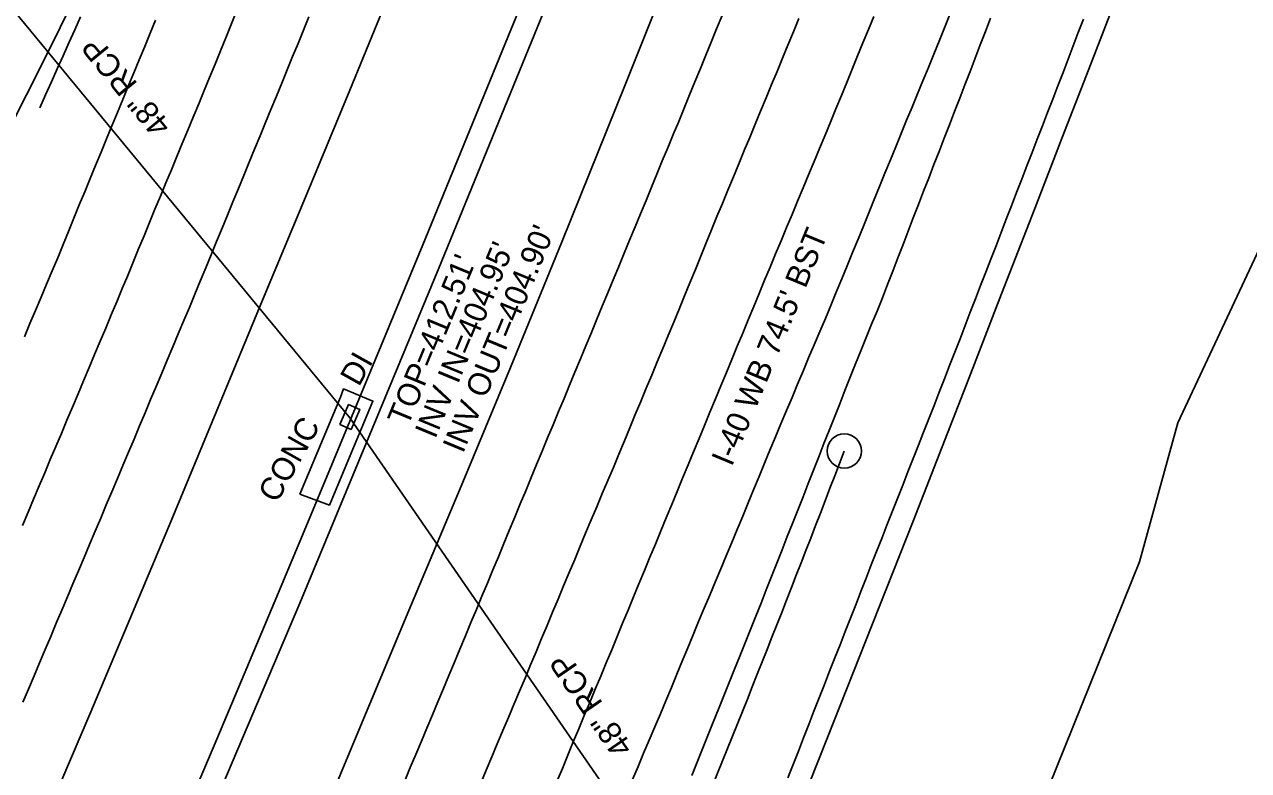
# Model space of a CAD drawing. Extents: x 2074109 to 2077820, y 741079 to 746031.
# Drawn here: x 2076109.6 to 2076324, y 744579.2 to 744709.8 of the extents above; entities that cross this region are included whole.
import ezdxf

# ---------------------------------------------------------------- set-up
doc = ezdxf.new("R2010")
doc.units = 0
for name, color, linetype in [('Exist Guardrail Cable Guide Rail', 7, 'Continuous'), ('Exist Horizontal Alignment', 7, 'Continuous'), ('Exist Horizontal Alignment Point', 7, 'Continuous'), ('Exist Roads EOP', 7, 'Continuous'), ('Exist Roads EOP Text', 7, 'Continuous'), ('Exist Roads EOT', 7, 'Continuous'), ('Exist Structure Minor Drop Inlet', 7, 'Continuous'), ('Exist Structure Minor Drop Inlet Text', 7, 'Continuous'), ('Exist Structure Minor Drop Inlet Top Elevation', 7, 'Continuous'), ('Exist Structure Minor Paved Ditch or Gutter', 7, 'Continuous'), ('Exist Structure Minor Paved Ditch or Gutter Text', 7, 'Continuous'), ('Exist Structure Minor Pipes RCP 48 Inch', 7, 'Continuous'), ('Exist Structure Minor Pipes RCP 48 Inch Invert', 7, 'Continuous'), ('Exist Structure Minor Pipes RCP 48 Inch Text', 7, 'Continuous'), ('Exist Vegetation Woods Line', 7, 'Continuous')]:
    doc.layers.add(name, color=color, linetype=linetype)

msp = doc.modelspace()

# ---------------------------------------------------------------- linework, layer by layer
at = {"layer": 'Exist Guardrail Cable Guide Rail'}
for points in [[(2076157.81, 744608.48), (2076182.17, 744667.13), (2076200.46, 744711.79), (2076224.74, 744772.31), (2076248.56, 744832.55), (2076283.35, 744922.09), (2076306.06, 744981.77), (2076321.31, 745022.08)], [(2075948.31, 744139.02), (2075989.39, 744226.34), (2076023.39, 744300.35), (2076049.61, 744359.61), (2076088.84, 744447.64), (2076120.46, 744520.55), (2076157.81, 744608.48)]]:
    msp.add_lwpolyline(points, dxfattribs=at)
at = {"layer": 'Exist Horizontal Alignment'}
for centre, radius, start, end in [((2065746.77, 748969.72), 11283.45, 330.581241, 339.398504), ((2074798.58, 745361.18), 1469.76, 306.18995, 339.08912), ((2073514.74, 745680.24), 2931.09, 337.65302, 339.11117)]:
    msp.add_arc(centre, radius, start, end, dxfattribs=at)
at = {"layer": 'Exist Horizontal Alignment Point'}
msp.add_circle((2076253.18, 744635.14), 3, dxfattribs=at)
at = {"layer": 'Exist Roads EOP'}
for points in [[(2076301.38, 744917.71), (2076290.05, 744888.4), (2076279.13, 744860.68), (2076268.89, 744834.6), (2076259.62, 744810.96), (2076250.46, 744787.8), (2076239.27, 744760.09), (2076226.77, 744729.15), (2076214.82, 744699.23), (2076203.77, 744671.9), (2076194.71, 744649.77), (2076186.11, 744628.98), (2076176.93, 744607.21), (2076166.52, 744582.37), (2076156.08, 744557.21), (2076146.17, 744533.97), (2076137.36, 744513.8), (2076127.55, 744490.96), (2076117.74, 744468.19), (2076107.5, 744444.68), (2076097.57, 744422.1), (2076087.78, 744400.15), (2076077.87, 744377.58), (2076066.3, 744351.92)], [(2076017.34, 744351.57), (2076024.53, 744367.7), (2076032.16, 744384.78), (2076040.54, 744403.58), (2076049.71, 744424.28), (2076058.18, 744443.41), (2076065.39, 744459.74), (2076072.98, 744477.03), (2076081.56, 744496.75), (2076090.68, 744517.93), (2076100.09, 744540.01), (2076106.65, 744555.4), (2076114.28, 744573.21), (2076121.23, 744589.47), (2076128.09, 744605.72), (2076135.28, 744622.91), (2076143.19, 744641.95), (2076151.31, 744661.52), (2076159.11, 744680.25), (2076166.6, 744698.31), (2076173.8, 744715.85)], [(2076299.7, 744711.5), (2076295.58, 744700.96), (2076291.35, 744690.03), (2076286.56, 744677.62), (2076280.74, 744662.65), (2076274.97, 744647.82), (2076270.34, 744635.86), (2076265.26, 744622.84), (2076258.12, 744604.87), (2076250.1, 744584.72), (2076242.34, 744565.18)]]:
    msp.add_lwpolyline(points, dxfattribs=at)
at = {"layer": 'Exist Roads EOT'}
for points in [[(2076109.27, 744622.11), (2076110.24, 744624.42), (2076111.22, 744626.72), (2076112.19, 744629.02), (2076113.16, 744631.32), (2076114.14, 744633.63), (2076115.12, 744635.93), (2076116.09, 744638.23), (2076117.06, 744640.54), (2076118.03, 744642.84), (2076119, 744645.14), (2076119.97, 744647.45), (2076120.93, 744649.75), (2076121.9, 744652.06), (2076122.87, 744654.36), (2076123.84, 744656.67), (2076124.81, 744658.97), (2076125.78, 744661.28), (2076126.75, 744663.58), (2076127.71, 744665.89), (2076128.66, 744668.2), (2076129.61, 744670.51), (2076130.56, 744672.83), (2076131.51, 744675.14), (2076132.47, 744677.45), (2076133.43, 744679.76), (2076134.38, 744682.07), (2076135.34, 744684.38), (2076136.3, 744686.68), (2076137.25, 744688.99), (2076138.21, 744691.3), (2076139.17, 744693.61), (2076140.12, 744695.92), (2076141.08, 744698.23), (2076142.04, 744700.54), (2076142.99, 744702.85), (2076143.93, 744705.17), (2076144.87, 744707.48), (2076145.82, 744709.8), (2076146.76, 744712.11)], [(2076159.44, 744711.12), (2076158.49, 744708.81), (2076157.53, 744706.5), (2076156.58, 744704.19), (2076155.63, 744701.88), (2076154.68, 744699.56), (2076153.73, 744697.25), (2076152.78, 744694.94), (2076151.83, 744692.63), (2076150.88, 744690.32), (2076149.92, 744688), (2076148.97, 744685.69), (2076148.02, 744683.38), (2076147.07, 744681.07), (2076146.12, 744678.76), (2076145.17, 744676.44), (2076144.22, 744674.13), (2076143.27, 744671.82), (2076142.31, 744669.51), (2076141.36, 744667.2), (2076140.41, 744664.89), (2076139.46, 744662.57), (2076138.49, 744660.27), (2076137.52, 744657.96), (2076136.55, 744655.66), (2076135.59, 744653.35), (2076134.62, 744651.05), (2076133.65, 744648.74), (2076132.68, 744646.44), (2076131.71, 744644.13), (2076130.75, 744641.83), (2076129.78, 744639.52), (2076128.81, 744637.22), (2076127.84, 744634.92), (2076126.86, 744632.62), (2076125.89, 744630.31), (2076124.92, 744628.01), (2076123.94, 744625.71), (2076122.97, 744623.4), (2076122, 744621.1), (2076121.02, 744618.8), (2076120.05, 744616.5), (2076119.08, 744614.19), (2076118.1, 744611.89), (2076117.13, 744609.59), (2076116.15, 744607.29), (2076115.18, 744604.98), (2076114.21, 744602.68), (2076113.24, 744600.38), (2076112.26, 744598.07), (2076111.29, 744595.77), (2076110.32, 744593.47), (2076109.35, 744591.17)], [(2076112.29, 744695.2), (2076113.31, 744697.48), (2076114.33, 744699.76), (2076115.35, 744702.04), (2076116.37, 744704.33), (2076117.39, 744706.61), (2076118.41, 744708.89), (2076119.44, 744711.17)], [(2076176.21, 744577.43), (2076177.18, 744579.73), (2076178.16, 744582.03), (2076179.13, 744584.33), (2076180.1, 744586.64), (2076181.06, 744588.94), (2076182.03, 744591.25), (2076182.99, 744593.56), (2076183.95, 744595.87), (2076184.91, 744598.18), (2076185.87, 744600.48), (2076186.83, 744602.79), (2076187.79, 744605.1), (2076188.76, 744607.41), (2076189.72, 744609.71), (2076190.68, 744612.02), (2076191.64, 744614.33), (2076192.6, 744616.64), (2076193.56, 744618.94), (2076194.52, 744621.25), (2076195.48, 744623.56), (2076196.44, 744625.87), (2076197.39, 744628.18), (2076198.35, 744630.49), (2076199.31, 744632.8), (2076200.27, 744635.11), (2076201.23, 744637.42), (2076202.19, 744639.73), (2076203.14, 744642.03), (2076204.1, 744644.34), (2076205.06, 744646.65), (2076206.02, 744648.96), (2076206.98, 744651.27), (2076207.94, 744653.58), (2076208.89, 744655.89), (2076209.85, 744658.2), (2076210.81, 744660.51), (2076211.77, 744662.82), (2076212.72, 744665.13), (2076213.68, 744667.44), (2076214.63, 744669.75), (2076215.59, 744672.06), (2076216.54, 744674.37), (2076217.5, 744676.68), (2076218.46, 744678.99), (2076219.41, 744681.3), (2076220.37, 744683.61), (2076221.32, 744685.92), (2076222.28, 744688.23), (2076223.23, 744690.54), (2076224.19, 744692.85), (2076225.14, 744695.16), (2076226.09, 744697.47), (2076227.03, 744699.79), (2076227.98, 744702.1), (2076228.93, 744704.41), (2076229.88, 744706.73), (2076230.83, 744709.04), (2076231.78, 744711.35)], [(2076245.21, 744710.84), (2076244.27, 744708.52), (2076243.32, 744706.21), (2076242.37, 744703.9), (2076241.41, 744701.59), (2076240.46, 744699.28), (2076239.5, 744696.97), (2076238.54, 744694.66), (2076237.59, 744692.35), (2076236.63, 744690.04), (2076235.67, 744687.73), (2076234.72, 744685.42), (2076233.76, 744683.11), (2076232.8, 744680.8), (2076231.85, 744678.49), (2076230.89, 744676.18), (2076229.93, 744673.87), (2076228.98, 744671.56), (2076228.04, 744669.25), (2076227.1, 744666.93), (2076226.16, 744664.61), (2076225.23, 744662.29), (2076224.27, 744659.98), (2076223.31, 744657.68), (2076222.35, 744655.37), (2076221.39, 744653.06), (2076220.43, 744650.75), (2076219.47, 744648.44), (2076218.51, 744646.13), (2076217.55, 744643.82), (2076216.59, 744641.52), (2076215.63, 744639.21), (2076214.67, 744636.9), (2076213.71, 744634.59), (2076212.75, 744632.28), (2076211.77, 744629.98), (2076210.8, 744627.68), (2076209.83, 744625.38), (2076208.86, 744623.07), (2076207.89, 744620.77), (2076206.93, 744618.46), (2076205.97, 744616.15), (2076205, 744613.85), (2076204.04, 744611.54), (2076203.07, 744609.23), (2076202.11, 744606.93), (2076201.14, 744604.62), (2076200.18, 744602.31), (2076199.21, 744600.01), (2076198.25, 744597.7), (2076197.28, 744595.4), (2076196.31, 744593.09), (2076195.33, 744590.79), (2076194.36, 744588.49), (2076193.39, 744586.19), (2076192.42, 744583.88), (2076191.45, 744581.58), (2076190.48, 744579.27), (2076189.52, 744576.97)], [(2076258.36, 744711.23), (2076257.41, 744708.92), (2076256.45, 744706.61), (2076255.5, 744704.3), (2076254.55, 744701.99), (2076253.61, 744699.67), (2076252.67, 744697.35), (2076251.73, 744695.04), (2076250.77, 744692.73), (2076249.81, 744690.42), (2076248.85, 744688.11), (2076247.89, 744685.8), (2076246.93, 744683.49), (2076245.97, 744681.19), (2076245.01, 744678.88), (2076244.05, 744676.57), (2076243.08, 744674.26), (2076242.12, 744671.95), (2076241.16, 744669.65), (2076240.2, 744667.34), (2076239.24, 744665.03), (2076238.28, 744662.72), (2076237.32, 744660.41), (2076236.36, 744658.1), (2076235.41, 744655.79), (2076234.45, 744653.49), (2076233.49, 744651.18), (2076232.53, 744648.87), (2076231.58, 744646.56), (2076230.62, 744644.25), (2076229.66, 744641.94), (2076228.71, 744639.63), (2076227.75, 744637.32), (2076226.79, 744635.01), (2076225.83, 744632.7), (2076224.88, 744630.39), (2076223.92, 744628.08), (2076222.96, 744625.77), (2076222.01, 744623.46), (2076221.06, 744621.15), (2076220.1, 744618.84), (2076219.14, 744616.53), (2076218.19, 744614.22), (2076217.23, 744611.91), (2076216.27, 744609.6), (2076215.32, 744607.29), (2076214.36, 744604.98), (2076213.41, 744602.67), (2076212.45, 744600.36), (2076211.49, 744598.05), (2076210.54, 744595.74), (2076209.58, 744593.43), (2076208.62, 744591.12), (2076207.65, 744588.82), (2076206.69, 744586.51), (2076205.73, 744584.21), (2076204.77, 744581.9), (2076203.81, 744579.59), (2076202.86, 744577.27)], [(2076271.67, 744711.55), (2076270.73, 744709.23), (2076269.79, 744706.91), (2076268.85, 744704.6), (2076267.91, 744702.28), (2076266.95, 744699.97), (2076266, 744697.66), (2076265.05, 744695.35), (2076264.1, 744693.03), (2076263.15, 744690.72), (2076262.2, 744688.41), (2076261.26, 744686.1), (2076260.31, 744683.78), (2076259.37, 744681.46), (2076258.43, 744679.15), (2076257.49, 744676.83), (2076256.55, 744674.52), (2076255.6, 744672.2), (2076254.65, 744669.89), (2076253.7, 744667.58), (2076252.74, 744665.27), (2076251.79, 744662.96), (2076250.84, 744660.64), (2076249.87, 744658.34), (2076248.89, 744656.04), (2076247.92, 744653.74), (2076246.94, 744651.43), (2076245.97, 744649.13), (2076245, 744646.83), (2076244.03, 744644.52), (2076243.06, 744642.22), (2076242.09, 744639.91), (2076241.13, 744637.61), (2076240.16, 744635.3), (2076239.2, 744633), (2076238.25, 744630.68), (2076237.3, 744628.37), (2076236.35, 744626.06), (2076235.4, 744623.75), (2076234.45, 744621.43), (2076233.5, 744619.12), (2076232.52, 744616.82), (2076231.55, 744614.52), (2076230.58, 744612.21), (2076229.61, 744609.91), (2076228.63, 744607.61), (2076227.66, 744605.3), (2076226.71, 744602.99), (2076225.76, 744600.68), (2076224.81, 744598.37), (2076223.86, 744596.05), (2076222.91, 744593.74), (2076221.95, 744591.43), (2076220.97, 744589.13), (2076219.99, 744586.83), (2076219.01, 744584.53), (2076218.04, 744582.23), (2076217.06, 744579.93), (2076216.08, 744577.63)], [(2076226.5, 744578.36), (2076227.43, 744580.69), (2076228.35, 744583.01), (2076229.28, 744585.33), (2076230.21, 744587.65), (2076231.14, 744589.97), (2076232.08, 744592.29), (2076233.01, 744594.61), (2076233.94, 744596.93), (2076234.87, 744599.25), (2076235.8, 744601.57), (2076236.74, 744603.89), (2076237.67, 744606.21), (2076238.6, 744608.53), (2076239.53, 744610.85), (2076240.46, 744613.17), (2076241.37, 744615.5), (2076242.29, 744617.82), (2076243.2, 744620.15), (2076244.12, 744622.48), (2076245.04, 744624.8), (2076245.96, 744627.13), (2076246.87, 744629.45), (2076247.79, 744631.78), (2076248.71, 744634.1), (2076249.63, 744636.43), (2076250.55, 744638.75), (2076251.46, 744641.08), (2076252.38, 744643.4), (2076253.3, 744645.73), (2076254.22, 744648.05), (2076255.14, 744650.38), (2076256.07, 744652.7), (2076257.02, 744655.01), (2076257.97, 744657.32), (2076258.93, 744659.63), (2076259.85, 744661.96), (2076260.76, 744664.29), (2076261.66, 744666.62), (2076262.56, 744668.95), (2076263.47, 744671.28), (2076264.37, 744673.61), (2076265.27, 744675.94), (2076266.18, 744678.27), (2076267.08, 744680.6), (2076267.98, 744682.93), (2076268.89, 744685.27), (2076269.79, 744687.6), (2076270.7, 744689.93), (2076271.61, 744692.25), (2076272.51, 744694.58), (2076273.42, 744696.91), (2076274.31, 744699.25), (2076275.21, 744701.58), (2076276.11, 744703.92), (2076277, 744706.25), (2076277.9, 744708.58), (2076278.8, 744710.92)], [(2076295.06, 744710.73), (2076294.17, 744708.4), (2076293.27, 744706.06), (2076292.38, 744703.73), (2076291.49, 744701.39), (2076290.59, 744699.06), (2076289.68, 744696.73), (2076288.78, 744694.4), (2076287.88, 744692.06), (2076286.98, 744689.73), (2076286.07, 744687.4), (2076285.17, 744685.07), (2076284.27, 744682.74), (2076283.37, 744680.41), (2076282.47, 744678.08), (2076281.56, 744675.75), (2076280.66, 744673.41), (2076279.76, 744671.08), (2076278.86, 744668.75), (2076277.96, 744666.42), (2076277.05, 744664.09), (2076276.15, 744661.76), (2076275.25, 744659.42), (2076274.35, 744657.09), (2076273.45, 744654.76), (2076272.55, 744652.43), (2076271.64, 744650.1), (2076270.74, 744647.77), (2076269.83, 744645.44), (2076268.91, 744643.11), (2076267.99, 744640.79), (2076267.07, 744638.46), (2076266.16, 744636.14), (2076265.24, 744633.81), (2076264.32, 744631.49), (2076263.41, 744629.16), (2076262.49, 744626.83), (2076261.57, 744624.51), (2076260.66, 744622.18), (2076259.74, 744619.85), (2076258.83, 744617.53), (2076257.92, 744615.2), (2076257.01, 744612.87), (2076256.09, 744610.54), (2076255.18, 744608.22), (2076254.27, 744605.89), (2076253.36, 744603.56), (2076252.44, 744601.23), (2076251.53, 744598.91), (2076250.62, 744596.58), (2076249.71, 744594.25), (2076248.79, 744591.92), (2076247.88, 744589.6), (2076246.97, 744587.27), (2076246.05, 744584.94), (2076245.14, 744582.62), (2076244.23, 744580.29), (2076243.31, 744577.96)], [(2076132.57, 744710.57), (2076131.62, 744708.26), (2076130.67, 744705.94), (2076129.71, 744703.63), (2076128.76, 744701.32), (2076127.8, 744699.01), (2076126.85, 744696.7), (2076125.89, 744694.39), (2076124.94, 744692.08), (2076123.99, 744689.77), (2076123.03, 744687.46), (2076122.08, 744685.15), (2076121.12, 744682.84), (2076120.17, 744680.53), (2076119.22, 744678.22), (2076118.27, 744675.9), (2076117.33, 744673.59), (2076116.39, 744671.27), (2076115.43, 744668.96), (2076114.46, 744666.66), (2076113.48, 744664.35), (2076112.51, 744662.05), (2076111.54, 744659.75), (2076110.56, 744657.45), (2076109.59, 744655.14)]]:
    msp.add_lwpolyline(points, dxfattribs=at)
at = {"layer": 'Exist Structure Minor Drop Inlet'}
msp.add_lwpolyline([(2076164.84, 744639.76), (2076166.36, 744643.26), (2076168.32, 744642.42), (2076166.81, 744638.91)], close=True, dxfattribs=at)
at = {"layer": 'Exist Structure Minor Paved Ditch or Gutter'}
msp.add_lwpolyline([(2076157.86, 744627.59), (2076164.95, 744644.58), (2076165.51, 744646.01), (2076170.63, 744643.87), (2076163.01, 744625.68), (2076157.86, 744627.59)], dxfattribs=at)
at = {"layer": 'Exist Structure Minor Pipes RCP 48 Inch'}
for p in [(2076057.12, 744773.62), (2076249.68, 744520.7)]:
    msp.add_line(p, (2076166.6, 744640.93), dxfattribs=at)
at = {"layer": 'Exist Vegetation Woods Line'}
msp.add_lwpolyline([(2076277.39, 744547.61), (2076304.88, 744615.77), (2076311.59, 744640.07), (2076328.48, 744676.05), (2076334.39, 744699.16), (2076347.29, 744742.19), (2076362.36, 744774.71), (2076373.83, 744800.55), (2076388.5, 744841.52), (2076397.34, 744862.67), (2076406.52, 744897.73), (2076411.55, 744913.31), (2076426.2, 744955.64), (2076435.73, 744978.8)], dxfattribs=at)

# ---------------------------------------------------------------- texts
at = {"layer": 'Exist Roads EOP Text'}
msp.add_text("I-40 WB 74.5' BST", height=4, rotation=67.5312, dxfattribs=at).set_placement((2076233.48, 744632.28))
at = {"layer": 'Exist Structure Minor Drop Inlet Text'}
msp.add_text('DI', height=4, rotation=60.7411, dxfattribs=at).set_placement((2076168.19, 744646.26))
at = {"layer": 'Exist Structure Minor Drop Inlet Top Elevation'}
msp.add_text("TOP=412.51'", height=4, rotation=67.5205, dxfattribs=at).set_placement((2076176.75, 744639.31))
at = {"layer": 'Exist Structure Minor Paved Ditch or Gutter Text'}
msp.add_text('CONC', height=4, rotation=60.742, dxfattribs=at).set_placement((2076153.82, 744625.86))
at = {"layer": 'Exist Structure Minor Pipes RCP 48 Inch Invert'}
for s, p in [("INV OUT=404.90'", (2076186.41, 744634.58)), ("INV IN=404.95'", (2076181.55, 744637.13))]:
    msp.add_text(s, height=4, rotation=67.5205, dxfattribs=at).set_placement(p)
at = {"layer": 'Exist Structure Minor Pipes RCP 48 Inch Text'}
for rotation, p in [(129.3261, (2076135.47, 744692.18)), (124.6434, (2076216.31, 744583.27))]:
    msp.add_text('48" RCP', height=4, rotation=rotation, dxfattribs=at).set_placement(p)

doc.saveas('drawing.dxf')
